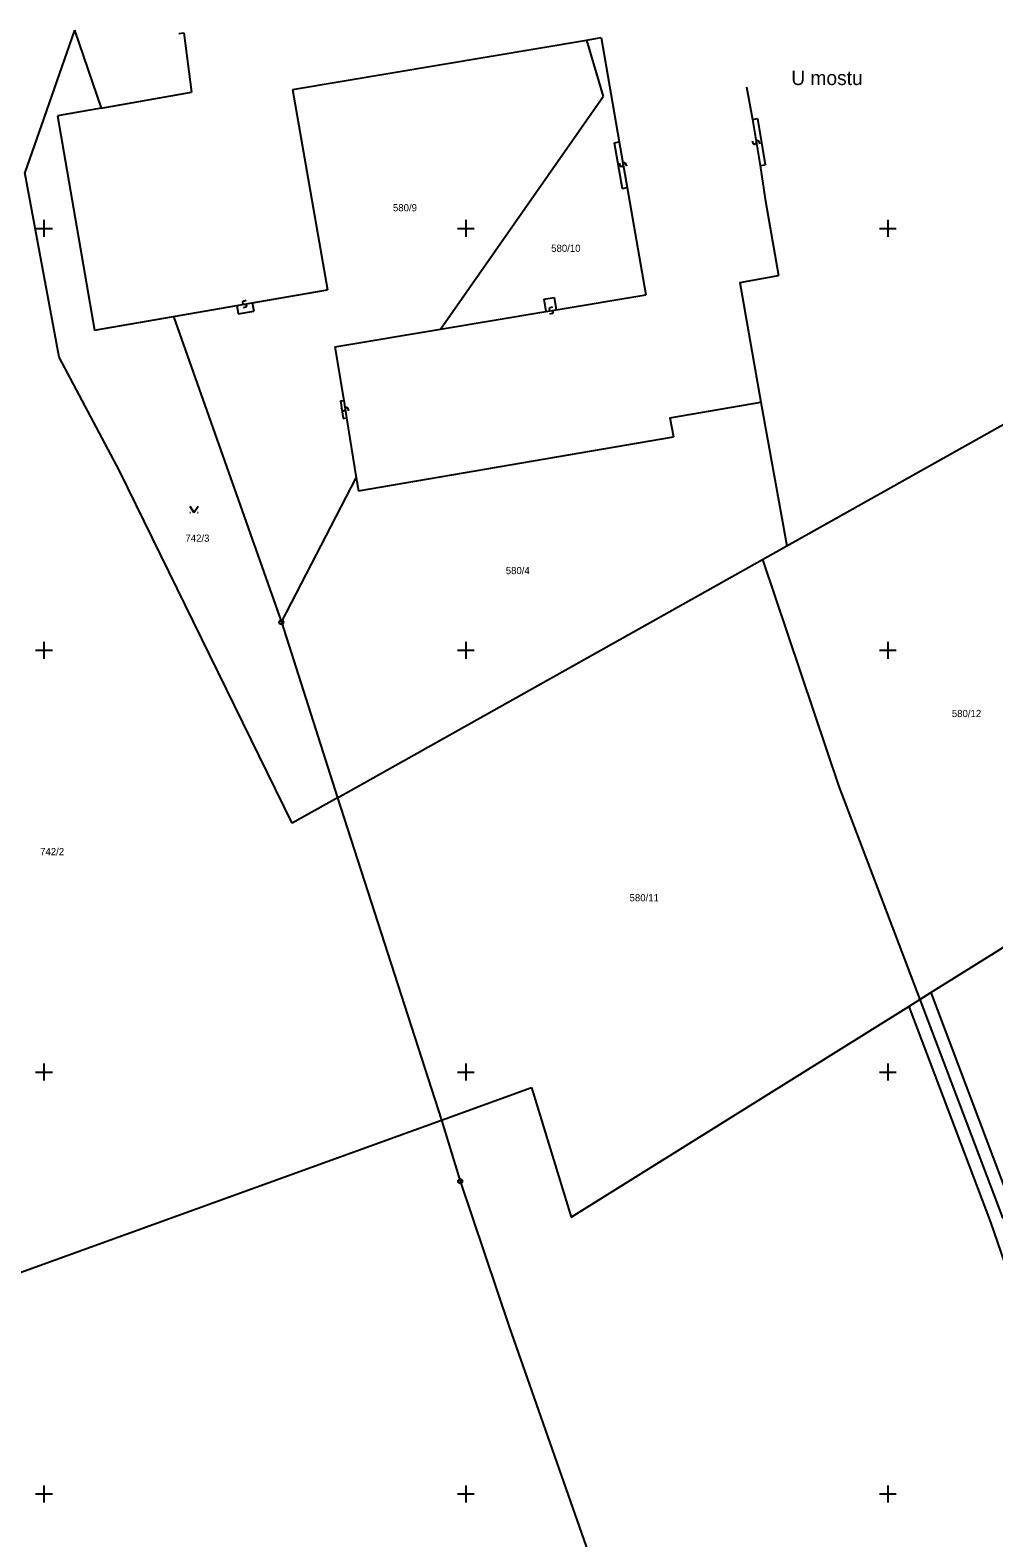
# Model space of a CAD drawing. Extents: x -493648 to -493033, y -1127718 to -1127026.
# Drawn here: x -493551.6 to -493437.4, y -1127205.2 to -1127026.5 of the extents above; entities that cross this region are included whole.
import ezdxf

# ---------------------------------------------------------------- set-up
doc = ezdxf.new("R2010")
doc.units = 0
doc.layers.add('katastrální mapa', color=7, linetype='Continuous')
doc.layers.add('síť', color=7, linetype='Continuous')

msp = doc.modelspace()

# ---------------------------------------------------------------- linework, layer by layer
at = {"layer": 'katastrální mapa'}
for p, q in [((-493546.37, -1127026.5), (-493550.01, -1127036.93)), ((-493546.37, -1127026.5), (-493543.2, -1127035.74)), ((-493546.37, -1127026.5), (-493543.2, -1127035.74)), ((-493534.02, -1127026.9), (-493533.42, -1127026.83)), ((-493533.42, -1127026.83), (-493532.52, -1127033.87)), ((-493520.53, -1127033.52), (-493485.72, -1127027.67)), ((-493485.72, -1127027.67), (-493483.98, -1127027.38)), ((-493485.72, -1127027.67), (-493483.73, -1127034.38)), ((-493483.98, -1127027.38), (-493481.83, -1127039.74)), ((-493543.2, -1127035.74), (-493532.52, -1127033.87)), ((-493520.53, -1127033.52), (-493516.39, -1127057.29)), ((-493503.01, -1127061.94), (-493483.73, -1127034.38)), ((-493466.75, -1127033.23), (-493466.05, -1127037.09)), ((-493543.2, -1127035.74), (-493548.39, -1127036.65)), ((-493543.2, -1127035.74), (-493548.39, -1127036.65)), ((-493548.39, -1127036.65), (-493543.99, -1127062.06)), ((-493548.39, -1127036.65), (-493543.99, -1127062.06)), ((-493550.01, -1127036.93), (-493552.26, -1127043.39)), ((-493466.05, -1127037.09), (-493465.46, -1127036.99)), ((-493466.05, -1127037.09), (-493465.13, -1127042.55)), ((-493465.46, -1127036.99), (-493464.54, -1127042.45)), ((-493482.42, -1127039.85), (-493481.83, -1127039.74)), ((-493482.42, -1127039.85), (-493481.48, -1127045.26)), ((-493481.83, -1127039.74), (-493480.89, -1127045.16)), ((-493465.92, -1127039.98), (-493466.03, -1127039.64)), ((-493465.8, -1127040.06), (-493465.92, -1127039.98)), ((-493465.7, -1127040.04), (-493465.8, -1127040.06)), ((-493465.62, -1127039.93), (-493465.7, -1127040.04)), ((-493465.56, -1127039.71), (-493465.62, -1127039.93)), ((-493465.48, -1127039.6), (-493465.56, -1127039.71)), ((-493465.38, -1127039.58), (-493465.48, -1127039.6)), ((-493465.26, -1127039.66), (-493465.38, -1127039.58)), ((-493465.15, -1127040), (-493465.26, -1127039.66)), ((-493548.19, -1127065.27), (-493552.26, -1127043.39)), ((-493481.69, -1127042.61), (-493481.8, -1127042.27)), ((-493481.57, -1127042.69), (-493481.69, -1127042.61)), ((-493481.47, -1127042.67), (-493481.57, -1127042.69)), ((-493481.39, -1127042.56), (-493481.47, -1127042.67)), ((-493481.33, -1127042.34), (-493481.39, -1127042.56)), ((-493481.25, -1127042.23), (-493481.33, -1127042.34)), ((-493481.15, -1127042.21), (-493481.25, -1127042.23)), ((-493481.03, -1127042.29), (-493481.15, -1127042.21)), ((-493480.92, -1127042.63), (-493481.03, -1127042.29)), ((-493465.13, -1127042.55), (-493464.54, -1127042.45)), ((-493465.13, -1127042.55), (-493464.54, -1127046.55)), ((-493481.48, -1127045.26), (-493480.89, -1127045.16)), ((-493480.89, -1127045.16), (-493478.68, -1127057.87)), ((-493464.54, -1127046.55), (-493462.94, -1127055.59)), ((-493467.55, -1127056.4), (-493462.94, -1127055.59)), ((-493525.31, -1127058.83), (-493516.39, -1127057.29)), ((-493489.28, -1127059.65), (-493478.68, -1127057.87)), ((-493467.55, -1127056.4), (-493465.03, -1127070.59)), ((-493534.66, -1127060.45), (-493527.14, -1127059.15)), ((-493527.14, -1127059.15), (-493525.31, -1127058.83)), ((-493527.14, -1127059.15), (-493526.97, -1127060.14)), ((-493526.97, -1127060.14), (-493525.14, -1127059.82)), ((-493526.38, -1127058.66), (-493526.47, -1127058.78)), ((-493526.47, -1127058.78), (-493526.45, -1127058.88)), ((-493526.45, -1127058.88), (-493526.33, -1127058.96)), ((-493526.07, -1127059.32), (-493526.4, -1127059.43)), ((-493526.05, -1127058.55), (-493526.38, -1127058.66)), ((-493526.33, -1127058.96), (-493526.12, -1127059.02)), ((-493526.12, -1127059.02), (-493526, -1127059.1)), ((-493525.98, -1127059.2), (-493526.07, -1127059.32)), ((-493526, -1127059.1), (-493525.98, -1127059.2)), ((-493525.31, -1127058.83), (-493525.14, -1127059.82)), ((-493503.01, -1127061.94), (-493490.52, -1127059.85)), ((-493490.76, -1127058.37), (-493489.53, -1127058.18)), ((-493490.76, -1127058.37), (-493490.52, -1127059.85)), ((-493490.52, -1127059.85), (-493489.28, -1127059.65)), ((-493490.05, -1127059.42), (-493490.14, -1127059.54)), ((-493490.14, -1127059.54), (-493490.12, -1127059.63)), ((-493490.12, -1127059.63), (-493490.01, -1127059.72)), ((-493489.72, -1127059.32), (-493490.05, -1127059.42)), ((-493490.01, -1127059.72), (-493489.79, -1127059.78)), ((-493489.79, -1127059.78), (-493489.68, -1127059.87)), ((-493489.68, -1127059.87), (-493489.66, -1127059.96)), ((-493489.53, -1127058.18), (-493489.28, -1127059.65)), ((-493543.99, -1127062.06), (-493534.66, -1127060.45)), ((-493543.99, -1127062.06), (-493534.66, -1127060.45)), ((-493534.66, -1127060.45), (-493521.86, -1127096.68)), ((-493534.66, -1127060.45), (-493521.86, -1127096.68)), ((-493489.75, -1127060.08), (-493490.08, -1127060.18)), ((-493489.66, -1127059.96), (-493489.75, -1127060.08)), ((-493515.52, -1127064.04), (-493503.01, -1127061.94)), ((-493541.05, -1127078.75), (-493548.19, -1127065.27)), ((-493515.52, -1127064.04), (-493514.47, -1127070.39)), ((-493514.87, -1127070.45), (-493514.47, -1127070.39)), ((-493514.87, -1127070.45), (-493514.53, -1127072.54)), ((-493514.47, -1127070.39), (-493514.13, -1127072.47)), ((-493475.81, -1127072.47), (-493465.03, -1127070.59)), ((-493465.03, -1127070.59), (-493461.97, -1127087.61)), ((-493514.63, -1127071.59), (-493514.74, -1127071.25)), ((-493514.51, -1127071.67), (-493514.63, -1127071.59)), ((-493514.42, -1127071.65), (-493514.51, -1127071.67)), ((-493514.33, -1127071.54), (-493514.42, -1127071.65)), ((-493514.27, -1127071.32), (-493514.33, -1127071.54)), ((-493514.18, -1127071.21), (-493514.27, -1127071.32)), ((-493514.09, -1127071.19), (-493514.18, -1127071.21)), ((-493513.97, -1127071.27), (-493514.09, -1127071.19)), ((-493513.86, -1127071.61), (-493513.97, -1127071.27)), ((-493461.97, -1127087.61), (-493432.84, -1127071.26)), ((-493514.53, -1127072.54), (-493514.13, -1127072.47)), ((-493514.13, -1127072.47), (-493512.98, -1127079.55)), ((-493475.81, -1127072.47), (-493475.41, -1127074.72)), ((-493512.73, -1127081.1), (-493475.41, -1127074.72)), ((-493520.59, -1127120.51), (-493541.05, -1127078.75)), ((-493521.86, -1127096.68), (-493512.98, -1127079.55)), ((-493512.98, -1127079.55), (-493512.73, -1127081.1)), ((-493532.72, -1127082.91), (-493532.22, -1127083.66)), ((-493532.22, -1127083.66), (-493531.72, -1127082.91)), ((-493532.72, -1127083.66), (-493532.62, -1127083.66)), ((-493531.82, -1127083.66), (-493531.72, -1127083.66)), ((-493464.85, -1127089.23), (-493461.97, -1127087.61)), ((-493515.2, -1127117.49), (-493464.85, -1127089.23)), ((-493464.85, -1127089.23), (-493455.8, -1127116.13)), ((-493521.86, -1127096.68), (-493515.2, -1127117.49)), ((-493521.86, -1127096.68), (-493515.2, -1127117.49)), ((-493455.8, -1127116.13), (-493446.22, -1127141.41)), ((-493515.2, -1127117.49), (-493520.59, -1127120.51)), ((-493515.2, -1127117.49), (-493502.87, -1127155.68)), ((-493515.2, -1127117.49), (-493502.87, -1127155.68)), ((-493444.9, -1127140.58), (-493415.8, -1127122.41)), ((-493447.5, -1127142.21), (-493446.22, -1127141.41)), ((-493446.22, -1127141.41), (-493444.9, -1127140.58)), ((-493446.22, -1127141.41), (-493436.38, -1127167.36)), ((-493444.9, -1127140.58), (-493435.05, -1127166.63)), ((-493487.51, -1127167.19), (-493447.5, -1127142.21)), ((-493447.5, -1127142.21), (-493437.82, -1127167.8)), ((-493502.87, -1127155.68), (-493492.21, -1127151.82)), ((-493492.21, -1127151.82), (-493487.51, -1127167.19)), ((-493565.47, -1127178.34), (-493502.87, -1127155.68)), ((-493502.87, -1127155.68), (-493500.67, -1127162.94)), ((-493502.87, -1127155.68), (-493500.67, -1127162.94)), ((-493500.67, -1127162.94), (-493494.88, -1127180.18)), ((-493500.67, -1127162.94), (-493494.88, -1127180.18)), ((-493437.82, -1127167.8), (-493404.97, -1127263.84)), ((-493494.88, -1127180.18), (-493480.54, -1127221.06)), ((-493494.88, -1127180.18), (-493480.54, -1127221.06))]:
    msp.add_line(p, q, dxfattribs=at)
for centre, radius in [((-493521.86, -1127096.68), 0.25), ((-493521.86, -1127096.68), 0.005), ((-493500.67, -1127162.94), 0.25), ((-493500.67, -1127162.94), 0.005)]:
    msp.add_circle(centre, radius, dxfattribs=at)
at = {"layer": 'síť'}
for p, q in [((-493550, -1127049), (-493550, -1127051)), ((-493500, -1127049), (-493500, -1127051)), ((-493450, -1127049), (-493450, -1127051)), ((-493551, -1127050), (-493549, -1127050)), ((-493501, -1127050), (-493499, -1127050)), ((-493451, -1127050), (-493449, -1127050)), ((-493550, -1127099), (-493550, -1127101)), ((-493500, -1127099), (-493500, -1127101)), ((-493450, -1127099), (-493450, -1127101)), ((-493551, -1127100), (-493549, -1127100)), ((-493501, -1127100), (-493499, -1127100)), ((-493451, -1127100), (-493449, -1127100)), ((-493550, -1127149), (-493550, -1127151)), ((-493500, -1127149), (-493500, -1127151)), ((-493450, -1127149), (-493450, -1127151)), ((-493551, -1127150), (-493549, -1127150)), ((-493501, -1127150), (-493499, -1127150)), ((-493451, -1127150), (-493449, -1127150)), ((-493550, -1127199), (-493550, -1127201)), ((-493500, -1127199), (-493500, -1127201)), ((-493450, -1127199), (-493450, -1127201)), ((-493551, -1127200), (-493549, -1127200)), ((-493501, -1127200), (-493499, -1127200)), ((-493451, -1127200), (-493449, -1127200))]:
    msp.add_line(p, q, dxfattribs=at)

# ---------------------------------------------------------------- texts
at = {"layer": 'katastrální mapa'}
for s, height, p in [('U mostu', 1.699998, (-493461.44, -1127033.01)), ('580/9', 0.849996, (-493508.64, -1127047.97)), ('580/10', 0.849996, (-493489.89, -1127052.78)), ('742/3', 0.849996, (-493533.23, -1127087.14)), ('580/4', 0.849996, (-493495.27, -1127090.98)), ('580/12', 0.849996, (-493442.41, -1127107.92)), ('742/2', 0.849996, (-493550.45, -1127124.29)), ('580/11', 0.849996, (-493480.6, -1127129.76))]:
    msp.add_text(s, height=height, dxfattribs=at).set_placement(p)

doc.saveas('drawing.dxf')
